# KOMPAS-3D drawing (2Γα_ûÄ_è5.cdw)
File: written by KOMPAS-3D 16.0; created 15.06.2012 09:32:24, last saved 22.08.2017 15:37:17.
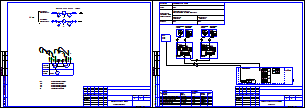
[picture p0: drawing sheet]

Sheets 1-2: A3, landscape

Title block, sheet 1: name: г. Москва, ул. Нежинская, д. 14, к.8 (кв. 1 и кв. 2); sheet number: 1; sheets: 27 / 28; sheet format: A3; stored path: D:\Проекты\Лыткарино\ул. Квартал 3А, д.25\710.74 РП.cdw; cell 320: Р
Title block, sheet 2: sheet number: 2

Views: Вид 2, Вид 3, Вид 4, Вид 5
Referenced files in C:\Program Files (x86)\ASCON\KOMPAS-3D V16\Sys\: SPDS.lcs, EngSys.lcs, GRAPHIC.LHS
Referenced files: graphic.tdp
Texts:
  МО, Клинский район, д. Решетниково, ул. Центральная, д.14
  GOST Common
  Normal
  List Paragraph
  heading 3
  для схемы
  txt
  краны
  Фоновая заливка
  Т0-элементы
  ВРУ
  Плата подключений
  СБ МКТС
  Pt 100
  Преобразователь
  температуры
  давления
  UP+
  UP-
  ИМП
  Лин
  Измерительный
  модуль М121
  Агрегат
  Системный блок  МКТС
  Среда
  Вода
  параметра и место
  отбора импульса
  Учет тепловой энергии и
  теплоносителя системы отопления
  Подающий
  трубопровод
  отопления
  Обратный
  ИМ1
  ИМ2
  каб.
  Начало
  трассы
  Трассы
  Марка
  Проложен
  Датчик температуры (Т1)
  Датчик температуры (Т2)
  Датчик давления (Т1)
  Датчик давления (Т2)
  Изм. модуль (Т2)
  Изм. модуль (Т1)
  ВРУ 220В, 50 Гц
  ИМ1 УУТЭ
  ИМ2 УУТЭ
  ИМ (Т1)
  FTP
  ПВС
  Конец
  Кол-во и
  сеч. жил
  Длина,
  Преобразователь расхода
  Термопреобразователь
  Преобразователь давления
  Преобразователь цифровой
  Системный блок МКТС
  приборы
  по месту
  шкаф
  учета
  UQIES
  УУТЭ
  Функциональная схема
  Размеры, параметризация
  сит. план
  подача ГВС
  обратка ГВС
  хвс
  обратка
  POLYLINE_STYLE_0.25_RGB_0_0_0
  стены
  Основная (не является границей для штриховки)
  POLYLINE_STYLE_0.18_RGB_0_0_0
  ХВС
  зеленая
  Красная тонкая
  арматура
  Подача
  Скрытая линия
  Ось Z
  Ось Y
  Ось X
  Образующая трубопровода (проектируемого)
  Трубопровод толщиной 0.6мм (одна линия)
  Трубопровод толщиной 1.2мм (одна линия)
  Трубопровод толщиной 1.0мм (одна линия)
  Трубопровод толщиной 0.8мм (одна линия)
  Трубопровод существующий (одна линия)
  Трубопровод невидимый (одна линия)
  Трубопровод демонтируемый (одна линия)
  Осевая трубопровода
  Осевая трубопровода (демонтируемого)
  Образующая трубопровода (существующего)
  Образующая трубопровода (невидимого)
  Изолированный трубопровод проектируемый (одна линия)
  Изолированный трубопровод существующий (одна линия)
  Образующая изоляции
  Изоляция
  Изолированный трубопровод невидимый (одна линия)
  Штрих пвс 075
  штрих пвс 2,5
  существующее оборудование
  Существующее оборудование
  K5LT_BASIC_RGB_0_0_255_THICK_0.53
  POLYLINE_STYLE_1.51_RGB_0_0_255
  POLYLINE_STYLE_0.50_RGB_128_128_128
  K5LT_AXLED_RGB_255_128_0_SC_1_THICK_0.18
  ACAD_ISO04W100_RGB_0_0_0_SC_1_THICK_0.18
  тонкая черная
  пломбировка
  Провода
  синий штрих
  Стили документа
  G2co
  расход вторичной воды объемный
  расход вторичной воды объемный при 70гр
  Gco
  расход теплоносителя массовый
  расход теплоносит объемн подающ
  расход теплоносит объемн обр
  Лапир
  Ghvs
  Im1
  Im2
  Im3
  Im4
  Im5
  Khvs
  норматив ХВС
  число подъездов
  число этажей
  Nkv
  число квартир
  тепловая нагрузка на отопление
  сумма Q
  Qgvs
  тепловая нагрузка ГВС
  тепловая нагрузка на циркуляцию ГВС
  иммитовставка или под манометр
  ro1
  ro2
  ro3
  ro4
  верх предел темп граф
  нижн предел темп граф
  темп подачи ГВС
  темп обр ГВС
  темр хол воды
  vzdh
  Kchn
  Ktp
  Knp
  beta
  tnv
  Vклап
  KLP
  RPD
  RDS
  PUMP
  ro5
  Переход К-76 x 3-38 x 2-09Г2С ГОСТ 17378-2001
  Переход ГОСТ 17378-2001
  Переход
  ГОСТ
  Сталь 09Г2С ГОСТ 19281-89
  Переход К-76 x 3-45 x 2,5-09Г2С ГОСТ 17378-2001
  Переход К-57 x 3-38 x 2-09Г2С ГОСТ 17378-2001
  Переход К-57 x 3-32 x 2-09Г2С ГОСТ 17378-2001
  Втулка 20x50
  Переход К-108 x 4-57 x 3-09Г2С ГОСТ 17378-2001
  Переход К-45 x 2,5-32 x 2-09Г2С ГОСТ 17378-2001
  Переход К-89 x 3,5-45 x 2,5-09Г2С ГОСТ 17378-2001
  Переход К-133 x 5-108 x 4-09Г2С ГОСТ 17378-2001
  Переход К-159 x 4,5-89 x 3,5-09Г2С ГОСТ 17378-2001
  Переход К-45 x 2,5-38 x 2-09Г2С ГОСТ 17378-2001
  Фланец 1-32-1 Ст3сп ГОСТ 12820-80
  Фланцы
  Фланец
  квадратный
  Ст3сп
  Ст3сп ГОСТ 380-2005
  Переход К-57 x 3-45 x 2,5-09Г2С ГОСТ 17378-2001
  Переход К-76 x 3-57 x 3-09Г2С ГОСТ 17378-2001
  Фланец 1-50-16 Ст3сп ГОСТ 12821-80
  Переход К-89 x 3,5-76 x 3,5-09Г2С ГОСТ 17378-2001
  Переход К-108 x 4-89 x 3,5-09Г2С ГОСТ 17378-2001
  Тройник 159 x 4,5-09Г2С ГОСТ 17376-2001
  Тройники ГОСТ 17376-2001
  Тройник
  Отвод 90-159 x 4-09Г2С ГОСТ 17375-2001
  Отвод ГОСТ 17375-2001
  Отвод
  Переход К-108 x 4-76 x 3,5-09Г2С ГОСТ 17378-2001
  Переход К-159 x 4,5-108 x 4-09Г2С ГОСТ 17378-2001
  Переход К-133 x 5-76 x 3,5-09Г2С ГОСТ 17378-2001
  Переход К-133 x 4-89 x 3,5-09Г2С ГОСТ 17378-2001
  Переход К-1-42,4 x 2,6-21,3 x 2-TS10 ГОСТ 17378-2001
  TS10
  Сталь TS10 ИСО 2604/2-75
  Фланец 1-20-16 Ст3сп ГОСТ 12820-80
  Лит-Масса-Масштаб
  Материал-Предприятие
  Title Specification
  Body Specification ( left align )
  Body Specificaton ( centered )
  Поз.
  Кол.
  Приме-
  чание
  Таблица спецификации
  Засыпка
  Штрих3
  Штрих2
  Штрих1
  Песок
  Штр0.5пр7
  Штр0.5пр12
  Штр0.3пр10
  Штр1.4пр21.21
  Штр1пр15
  Штр2.12пр35
  Штр1.5пр25
  Штр2.82пр42.42
  Штр2пр30
  SACNCR_ISO 1
  Электрощитовая
  Пр-1
  Ок-1
  вапвыапвы
  Обозначение стандарта
  Типоразмер
  Разраб.
  Пров.
  Т.контр.
  Н.контр.
  Утв.
  автоматизации
  Рабочие чертежи основного комплекта. ГОСТ Р 21.1101-2009 Ф3
  Стадия
  Лист
  Листов
  Изм.
  Кол.уч.
  №док.
  Подп.
  Дата
  Изменение
  Номер документа
  Подпись
  Наименование объекта строительства, в состав которого входит здание, наим. микр
  Наименование здания (сооружения)
  Порядковый номер листа
  Количество листов в документе
  Наименование изображения
  Индекс предприятия, выпускающего документ
  Инв. № подл.
  Подп. и дата
  Взам. инв. №
  Инвентарный номер подлинника
  Подпись принявшего подлинник на хранение
  Инвентарный номер подлинника, взамен которого выпущен данный подлинник
  Согласовано
  Формат листа
  Согласование
  03 Рабочие чертежи основного комплекта. ГОСТ Р 21.1101-2009 Ф3
  Схема соединений внешних
  проводок
Dimensions and other numbers on the sheet: 0; 220В; 50Гц; 1; 2; 3; 6; 5; 4; 4-20; 2x2x0,52; 3х0,75; 15; 25; 9; 1,2; 3,4; 5,6; 7,8; 10; 7; 8; 4,0; 2,6582; 0,0160; 16; 95; 2,6160; 3,0; 70; 09Г2С; 12; 17; 19; 20; 21; 22; 23; 24; 26; 30; 31; 33; 34; 52; 64; 65; 66; 67; 69; 71; 72; 73; 74; 75; 27; 28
